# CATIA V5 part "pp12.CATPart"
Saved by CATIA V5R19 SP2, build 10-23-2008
Part number: pp12
Publications: "Plane.2"
Bounding box of the stored display mesh (mm): x 10 to 15, y 49.776 to 102.25, z 24.678 to 52.25
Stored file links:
  C:\Users\Welcome\Documents\thinkm2\pp12.CATPart
  C:\Users\Welcome\Documents\thinkm2\Brasmeca.CATProduct
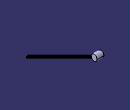
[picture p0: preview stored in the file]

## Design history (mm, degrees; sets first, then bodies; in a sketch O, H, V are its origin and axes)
AxisSystem1: origin (0, 0, 0), X (1, 0, 0), Y (0, 1, 0), Z (0, 0, 1)
Set1
  Plane1: linked copy from another document
  Line1: linked copy from another document
  Point1: linked copy from another document
  Line2: linked copy from another document
Body1 (main body)
  Sketch1 on Plane1, origin (15, 0, 0), H (0, 1, 0), V (0, 0, 1)
    circle A1 centre (100, 50) radius 2.25
    reference projected point E1 (100, 50) from Line1
    radius A1 = 2.25
    distance A1 E1 = 2.25
  Pad1: profile Sketch1, direction (-1, 0, 0), length 5
  Plane2: type Normal, Curve Line2, RefPoint Point1
  Sketch2 on Plane2, origin (0, 50, 25), H (1, 0, 0), V (0, -0.4472, 0.8944)
    line L1 (13.1167, 0.5) -> (14.8357, 0.5)
    line L2 (14.8357, 0.5) -> (14.8357, -0.36)
    line L3 (14.8357, -0.36) -> (13.1167, -0.36)
    line L4 (13.1167, -0.36) -> (13.1167, 0.5)
  Pad2: profile Sketch2, direction (0, 0.8944, 0.4472), length 54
